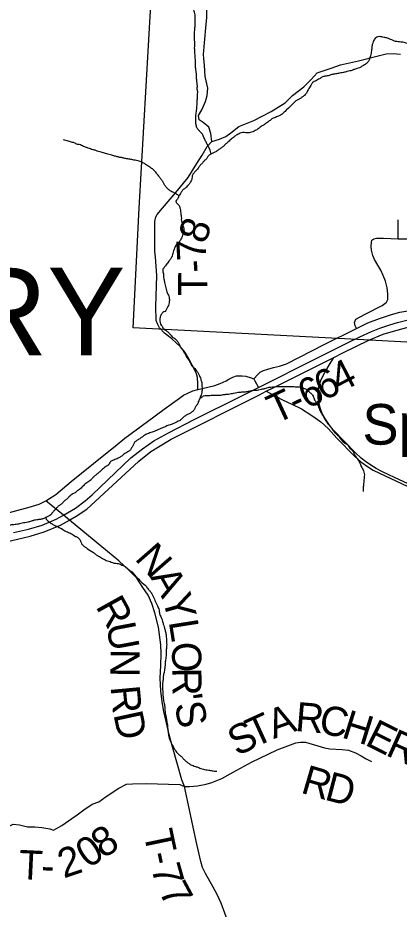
# Model space of a CAD drawing. Extents: x -20.2 to 34, y 0 to 22.
# Drawn here: x 4.435 to 5.177, y 14.901 to 16.636 of the extents above; entities that cross this region are included whole.
import ezdxf

# ---------------------------------------------------------------- set-up
doc = ezdxf.new("R2010")
doc.units = 0
for name, color, linetype in [('GM_X_County_Road', 7, 'Continuous'), ('GM_X_Minor_River', 7, 'Continuous'), ('GM_X_Section', 7, 'Continuous'), ('GM_X_State_Route', 7, 'Continuous'), ('GM_X_Township_Road', 7, 'Continuous'), ('GM_X_Township_Road_Text', 7, 'Continuous'), ('GM_X_Township_Text', 7, 'Continuous'), ('GM_X_Unincorporated_Text', 7, 'Continuous'), ('GM_X_US_Route', 7, 'Continuous')]:
    doc.layers.add(name, color=color, linetype=linetype)

msp = doc.modelspace()

# ---------------------------------------------------------------- linework, layer by layer
at = {"layer": 'GM_X_County_Road'}
for points in [[(4.4893, 15.6954), (4.5091, 15.7083), (4.5389, 15.7332), (4.6022, 15.7848), (4.6247, 15.8024), (4.6436, 15.8178), (4.6875, 15.8504), (4.7196, 15.8739), (4.7498, 15.8957), (4.7578, 15.9016), (4.7659, 15.9053), (4.7759, 15.9099), (4.7857, 15.9123), (4.8049, 15.917), (4.8188, 15.92), (4.8287, 15.9241), (4.8407, 15.9293), (4.8455, 15.9326), (4.8538, 15.9365), (4.8607, 15.9387), (4.8716, 15.9391), (4.8791, 15.938), (4.8893, 15.9352), (4.8947, 15.9332), (4.8964, 15.9292), (4.9034, 15.9164)], [(4.1832, 15.6019), (4.1857, 15.6029), (4.272, 15.6331), (4.426, 15.6752), (4.4573, 15.6834), (4.4765, 15.6894), (4.4893, 15.6954)]]:
    msp.add_lwpolyline(points, dxfattribs=at)
at = {"layer": 'GM_X_Minor_River'}
for points in [[(4.8114, 16.3706), (4.8086, 16.3802), (4.8049, 16.3871), (4.8015, 16.3943), (4.7981, 16.4008), (4.7952, 16.408), (4.7906, 16.4134), (4.7865, 16.4176), (4.7831, 16.4233), (4.7817, 16.4298), (4.7813, 16.4354), (4.7814, 16.4415), (4.7818, 16.4464), (4.7822, 16.451), (4.783, 16.4563), (4.7838, 16.4635), (4.7842, 16.4696), (4.7843, 16.4741), (4.7847, 16.4813), (4.7847, 16.4859), (4.7852, 16.4901), (4.7844, 16.4965), (4.7845, 16.5037), (4.7838, 16.5106), (4.7831, 16.5193), (4.7831, 16.5235), (4.7824, 16.5296), (4.7817, 16.5345), (4.781, 16.5391), (4.7806, 16.5444), (4.7807, 16.5516), (4.7804, 16.5573), (4.78, 16.5634), (4.7797, 16.5691), (4.7793, 16.574), (4.7794, 16.5858), (4.7791, 16.5922), (4.7793, 16.6123), (4.7797, 16.6169), (4.7801, 16.621), (4.7801, 16.626), (4.7802, 16.6381), (4.7795, 16.6442), (4.7784, 16.6488), (4.7769, 16.6537), (4.7735, 16.6587), (4.7675, 16.6659), (4.7596, 16.6732), (4.7536, 16.6808), (4.7487, 16.6866), (4.7431, 16.6927), (4.7344, 16.7003), (4.7299, 16.7049), (4.7242, 16.7092), (4.7152, 16.7157), (4.7072, 16.7207), (4.7, 16.7241), (4.6944, 16.7276), (4.6895, 16.7292), (4.6834, 16.7303), (4.6762, 16.7312), (4.6713, 16.7312), (4.6663, 16.7309), (4.6621, 16.7301), (4.658, 16.729), (4.6519, 16.7264), (4.6435, 16.7219), (4.6366, 16.7193), (4.6324, 16.7159), (4.6282, 16.7137), (4.6225, 16.7099), (4.6168, 16.7066), (4.6077, 16.7017), (4.6008, 16.6965), (4.5954, 16.6916), (4.5893, 16.6871), (4.5848, 16.6833), (4.579, 16.6792), (4.568, 16.6732), (4.5634, 16.6706), (4.5581, 16.6683), (4.5505, 16.6653), (4.5459, 16.6639), (4.5417, 16.6628), (4.5364, 16.6617), (4.5318, 16.6606), (4.5273, 16.6602), (4.522, 16.6603), (4.5178, 16.6599), (4.5121, 16.6596)], [(5.219, 16.5569), (5.2168, 16.5622), (5.2141, 16.5664), (5.2108, 16.5718), (5.2017, 16.5809), (5.1957, 16.5844), (5.1912, 16.5863), (5.187, 16.5875), (5.1824, 16.5883), (5.1783, 16.5887), (5.1726, 16.5895), (5.1684, 16.5903), (5.1631, 16.593), (5.159, 16.5942), (5.1548, 16.5961), (5.148, 16.5973), (5.1434, 16.5985), (5.1336, 16.5978), (5.1286, 16.5929), (5.1267, 16.5887), (5.1251, 16.5838), (5.1239, 16.5755), (5.1235, 16.5713), (5.1227, 16.5668), (5.1215, 16.5618), (5.1204, 16.5577), (5.1188, 16.5531), (5.1153, 16.5482), (5.11, 16.5441), (5.1054, 16.5415), (5.1001, 16.5385), (5.0948, 16.537), (5.0894, 16.5348), (5.0853, 16.5333), (5.0811, 16.5322), (5.0758, 16.5311), (5.0689, 16.5292), (5.0636, 16.5285), (5.0594, 16.5274), (5.0514, 16.5263), (5.0446, 16.5245), (5.0374, 16.5226), (5.0328, 16.5219), (5.0271, 16.5201), (5.0225, 16.5171), (5.0183, 16.5152), (5.0141, 16.5126), (5.01, 16.5107), (5.0065, 16.5062), (5.0042, 16.502), (5.0015, 16.4979), (4.9969, 16.4892), (4.9915, 16.4835), (4.987, 16.4801), (4.9824, 16.4771), (4.9778, 16.4749), (4.9728, 16.4708), (4.9583, 16.4565), (4.9522, 16.4508), (4.9465, 16.4463), (4.9408, 16.4437), (4.9366, 16.4418), (4.9324, 16.4403), (4.9274, 16.4373), (4.9217, 16.4325), (4.9068, 16.4227), (4.9026, 16.4197), (4.8973, 16.4163), (4.8927, 16.4137), (4.8874, 16.4122), (4.8828, 16.4115), (4.8787, 16.4119), (4.873, 16.4123), (4.868, 16.4109), (4.86, 16.4071), (4.8547, 16.403), (4.8478, 16.3974), (4.8413, 16.3913), (4.8364, 16.3868), (4.8318, 16.3827), (4.826, 16.3793), (4.8215, 16.3756), (4.8158, 16.3726), (4.8108, 16.3703), (4.8058, 16.3666), (4.8031, 16.362), (4.7978, 16.3571), (4.7944, 16.353), (4.7898, 16.3481), (4.7859, 16.3428), (4.781, 16.3375), (4.7771, 16.333), (4.7744, 16.3281), (4.774, 16.3232), (4.7725, 16.3186), (4.7702, 16.3145), (4.7663, 16.3092)], [(4.7489, 16.2888), (4.7434, 16.293), (4.737, 16.2961), (4.7328, 16.2981), (4.7276, 16.3023), (4.723, 16.3072), (4.72, 16.3118), (4.717, 16.3168), (4.7133, 16.3225), (4.7092, 16.3278), (4.7047, 16.3336), (4.699, 16.3401), (4.6918, 16.3451), (4.685, 16.3497), (4.6801, 16.3527), (4.6733, 16.3558), (4.6688, 16.3574), (4.6586, 16.3594), (4.6514, 16.3609), (4.6464, 16.3614), (4.64, 16.3629), (4.6332, 16.3641), (4.6271, 16.3657), (4.6199, 16.3676), (4.6157, 16.3688), (4.6104, 16.37), (4.6059, 16.3715), (4.5972, 16.3739), (4.5919, 16.3754), (4.587, 16.3774), (4.5809, 16.3789), (4.5722, 16.382), (4.565, 16.3844), (4.5571, 16.3882), (4.5514, 16.3894), (4.545, 16.3921), (4.5374, 16.3941), (4.5332, 16.3953), (4.5283, 16.3968), (4.5238, 16.3984)], [(4.7663, 16.3092), (4.7606, 16.3039), (4.7556, 16.3002), (4.7526, 16.2952), (4.7487, 16.2884), (4.7456, 16.2828), (4.7429, 16.2786), (4.7452, 16.2744), (4.7489, 16.2702), (4.7508, 16.2638), (4.7519, 16.2584), (4.7526, 16.2531), (4.7533, 16.2486), (4.7533, 16.2425), (4.754, 16.2372), (4.7555, 16.2326), (4.7574, 16.2284), (4.7585, 16.2231), (4.7584, 16.2185), (4.7557, 16.2125), (4.7542, 16.2083), (4.7507, 16.2015), (4.7465, 16.1966), (4.7423, 16.1929), (4.7404, 16.1887), (4.738, 16.1819), (4.7369, 16.1773), (4.7357, 16.1724), (4.733, 16.1675), (4.7291, 16.1618), (4.7238, 16.155), (4.7207, 16.1509), (4.7176, 16.1464), (4.7172, 16.1414), (4.7183, 16.1373), (4.7183, 16.1327), (4.7194, 16.1274), (4.7205, 16.1205), (4.7216, 16.1156), (4.7231, 16.1099), (4.7245, 16.1049), (4.726, 16.1004), (4.7283, 16.0958), (4.7294, 16.0916), (4.7301, 16.0874), (4.7297, 16.0833), (4.7293, 16.0783), (4.7273, 16.0738), (4.7246, 16.0685), (4.7216, 16.0644), (4.7174, 16.0621), (4.7135, 16.0565), (4.7116, 16.0504), (4.7116, 16.0455), (4.713, 16.0398), (4.7157, 16.0356), (4.7194, 16.0298), (4.7236, 16.0271), (4.7292, 16.0226), (4.733, 16.018), (4.7386, 16.0126), (4.7428, 16.0099), (4.7469, 16.0042), (4.7495, 15.9996), (4.7518, 15.9947), (4.7552, 15.9901), (4.7582, 15.9851), (4.7615, 15.9798), (4.7645, 15.9741), (4.7683, 15.9691), (4.7716, 15.9623), (4.7739, 15.9581), (4.7795, 15.9535), (4.7825, 15.9493), (4.7863, 15.9439), (4.7885, 15.939), (4.7904, 15.9348), (4.7915, 15.9306), (4.793, 15.9257), (4.7933, 15.9211), (4.7937, 15.9154), (4.7936, 15.9112), (4.7932, 15.9067), (4.7917, 15.9014), (4.7901, 15.8972), (4.7882, 15.893), (4.7863, 15.8881), (4.7839, 15.8828), (4.7805, 15.8779), (4.7785, 15.873), (4.7743, 15.8689), (4.7698, 15.8655), (4.7641, 15.8629), (4.7587, 15.8595), (4.7541, 15.855), (4.7495, 15.8516), (4.745, 15.8494)], [(4.7901, 15.8972), (4.7913, 15.8968), (4.7966, 15.8998), (4.8015, 15.9005), (4.8091, 15.9009), (4.8141, 15.9012), (4.8243, 15.9011), (4.8319, 15.9018), (4.8384, 15.9029), (4.8452, 15.9036), (4.8505, 15.9043), (4.8551, 15.9054), (4.8611, 15.9065), (4.8665, 15.9072), (4.8763, 15.9079), (4.8839, 15.909), (4.8896, 15.9101), (4.8949, 15.9108), (4.8991, 15.9108), (4.9037, 15.9115), (4.9094, 15.913), (4.9136, 15.9137), (4.9197, 15.9156), (4.9246, 15.9167), (4.9307, 15.9174), (4.9352, 15.9177), (4.9413, 15.9181), (4.9459, 15.918), (4.9523, 15.918), (4.9584, 15.9183), (4.9698, 15.9182), (4.9751, 15.9178), (4.98, 15.9174), (4.9853, 15.9169), (4.9902, 15.9154), (4.9951, 15.9135), (4.9993, 15.9104), (5.0042, 15.9062), (5.0087, 15.9012), (5.0121, 15.894), (5.0151, 15.8879), (5.0196, 15.8806), (5.0214, 15.8753), (5.0237, 15.8707), (5.0267, 15.865), (5.0308, 15.8581), (5.0386, 15.8456), (5.0432, 15.8406), (5.0462, 15.836), (5.0495, 15.8318), (5.0533, 15.8272), (5.059, 15.8223), (5.065, 15.8142), (5.071, 15.8089), (5.0789, 15.802), (5.0815, 15.7978), (5.0861, 15.7936), (5.0887, 15.789), (5.0921, 15.7833), (5.0969, 15.776), (5.0992, 15.7718), (5.1022, 15.7665), (5.1037, 15.7623), (5.107, 15.7562), (5.1089, 15.7516), (5.1096, 15.7463), (5.1088, 15.7365), (5.1079, 15.7274), (5.1075, 15.7228), (5.1075, 15.7137)], [(4.745, 15.8494), (4.74, 15.8471), (4.7355, 15.8449), (4.7313, 15.8434), (4.7271, 15.8423), (4.7229, 15.8404), (4.7179, 15.8382), (4.7134, 15.8363), (4.7077, 15.8337), (4.7027, 15.8318), (4.6985, 15.83), (4.694, 15.8285), (4.6898, 15.827), (4.6845, 15.8248), (4.6799, 15.8222), (4.6738, 15.8176), (4.6673, 15.8135), (4.6631, 15.8105), (4.66, 15.8052), (4.6573, 15.8003), (4.6543, 15.795), (4.6493, 15.7909), (4.6447, 15.7886), (4.6386, 15.7838), (4.6329, 15.78), (4.6283, 15.7774), (4.6238, 15.7759), (4.6196, 15.774), (4.6146, 15.771), (4.6119, 15.7665), (4.6077, 15.7631), (4.6035, 15.7605), (4.5959, 15.7533), (4.5909, 15.7492), (4.5856, 15.7447), (4.581, 15.7409), (4.5775, 15.7368), (4.5714, 15.7323), (4.5672, 15.7293), (4.5611, 15.7236), (4.555, 15.718), (4.5508, 15.7154), (4.5466, 15.7116), (4.5424, 15.7093), (4.5344, 15.7033), (4.5306, 15.6992), (4.5252, 15.6951), (4.5207, 15.6902), (4.5161, 15.6868), (4.5115, 15.683), (4.5077, 15.6785), (4.5035, 15.6743), (4.4992, 15.6687), (4.495, 15.6661), (4.4897, 15.6634), (4.4855, 15.6612), (4.4791, 15.6597), (4.4718, 15.6587), (4.4669, 15.6579), (4.4612, 15.6561), (4.4547, 15.6542), (4.4487, 15.6531), (4.4433, 15.652), (4.4384, 15.6509), (4.4342, 15.6502), (4.4297, 15.6495), (4.4247, 15.6491), (4.4205, 15.6484), (4.4137, 15.647), (4.4088, 15.6459), (4.4034, 15.644), (4.397, 15.6422), (4.3928, 15.6407), (4.3886, 15.6396), (4.3844, 15.6377), (4.3795, 15.6366), (4.3749, 15.6343), (4.37, 15.6329), (4.3616, 15.6322), (4.3567, 15.6315), (4.3517, 15.6323), (4.3468, 15.6334), (4.3426, 15.6331), (4.3381, 15.632), (4.3327, 15.6301), (4.3282, 15.6279), (4.3209, 15.6241), (4.316, 15.6211), (4.3095, 15.6185), (4.3042, 15.6171), (4.2993, 15.6167), (4.2886, 15.6145), (4.2844, 15.6134), (4.2791, 15.6123), (4.2745, 15.6116), (4.2662, 15.6094), (4.262, 15.6083)], [(4.4897, 15.6634), (4.4897, 15.6627), (4.4965, 15.6543), (4.5006, 15.6516), (4.5059, 15.6485), (4.5108, 15.6462), (4.5157, 15.6435), (4.5203, 15.6416), (4.5244, 15.6385), (4.5293, 15.6362), (4.5339, 15.6343), (4.5384, 15.6319), (4.543, 15.6293), (4.5471, 15.6266), (4.552, 15.6242), (4.5565, 15.6193), (4.558, 15.6147), (4.5606, 15.6101), (4.5648, 15.6067), (4.5697, 15.6032), (4.5822, 15.5952), (4.5863, 15.5917), (4.5916, 15.5883), (4.5958, 15.5863), (4.5999, 15.5836), (4.6052, 15.5809), (4.6094, 15.579), (4.6147, 15.5775), (4.6192, 15.5755), (4.6256, 15.5743), (4.6306, 15.5735), (4.6374, 15.5708), (4.6427, 15.5685), (4.6472, 15.5651), (4.6532, 15.5601), (4.6574, 15.5574), (4.6615, 15.5532), (4.6649, 15.5486), (4.6694, 15.5444), (4.6747, 15.5386), (4.6852, 15.5287), (4.6898, 15.5226), (4.6939, 15.518), (4.6973, 15.5119), (4.6999, 15.5069), (4.7017, 15.502), (4.7044, 15.4967), (4.707, 15.4917), (4.7085, 15.4875), (4.7099, 15.483), (4.711, 15.4761), (4.714, 15.4689), (4.7162, 15.4632), (4.7173, 15.459), (4.7192, 15.4529), (4.7207, 15.4476), (4.7225, 15.4411), (4.7233, 15.4369), (4.724, 15.4301), (4.7243, 15.4251), (4.7246, 15.421), (4.7246, 15.4111), (4.7237, 15.4012), (4.7237, 15.3971), (4.7233, 15.3917), (4.7225, 15.3864), (4.7221, 15.3823), (4.7216, 15.3747), (4.7208, 15.3682), (4.72, 15.3629), (4.7185, 15.3569), (4.718, 15.3508), (4.7172, 15.344), (4.7168, 15.3383), (4.7168, 15.3318), (4.7171, 15.3254), (4.7174, 15.3193), (4.7181, 15.3109), (4.7188, 15.3064), (4.7199, 15.3014), (4.7207, 15.2972), (4.721, 15.2915), (4.7217, 15.2855), (4.7224, 15.2798), (4.7235, 15.2748), (4.725, 15.2672), (4.7257, 15.2623), (4.7264, 15.257), (4.7268, 15.252), (4.7275, 15.2456), (4.7286, 15.2391), (4.7297, 15.2342), (4.7315, 15.2292), (4.7334, 15.225), (4.7364, 15.2193), (4.7394, 15.214), (4.7428, 15.2086)], [(4.7428, 15.2086), (4.7484, 15.2021), (4.7537, 15.1979), (4.7578, 15.1933), (4.7627, 15.1887), (4.7673, 15.1853), (4.7718, 15.1822), (4.7763, 15.1806), (4.7809, 15.1787), (4.7873, 15.1768), (4.7915, 15.1748), (4.7964, 15.1737), (4.8009, 15.1725), (4.8066, 15.1717), (4.8131, 15.1705), (4.8222, 15.1697)]]:
    msp.add_spline(points, degree=3, dxfattribs=at)
at = {"layer": 'GM_X_Section'}
msp.add_lwpolyline([(5.7813, 16.999), (5.7463, 16.4999), (5.7268, 16.1694), (5.7132, 15.9765), (5.0956, 16.0096), (4.6593, 16.0323), (4.6715, 16.2651), (4.6941, 16.6609), (4.7152, 17.053)], close=True, dxfattribs=at)
at = {"layer": 'GM_X_State_Route'}
msp.add_line((5.0503, 15.9748), (5.068, 15.9835), dxfattribs=at)
for points in [[(5.038, 15.9839), (5.0441, 15.987), (5.0779, 16.0039), (5.1009, 16.015), (5.1236, 16.0253), (5.1397, 16.0318), (5.159, 16.0385), (5.1741, 16.0427), (5.1949, 16.0477), (5.2159, 16.0515), (5.2377, 16.0534), (5.266, 16.0542), (5.2864, 16.0538), (5.3466, 16.0495), (5.3739, 16.0465), (5.3908, 16.045), (5.4035, 16.0438), (5.4473, 16.0399), (5.4997, 16.0343), (5.5459, 16.0297), (5.5577, 16.0285), (5.5796, 16.0263)], [(5.068, 15.9835), (5.1183, 16.0083), (5.1461, 16.0201), (5.1663, 16.0262), (5.1921, 16.0329), (5.2125, 16.0367), (5.2464, 16.0404), (5.2644, 16.0406), (5.2792, 16.0403), (5.2902, 16.0399), (5.3256, 16.0371), (5.3442, 16.0353)], [(4.524, 15.6675), (4.5473, 15.6815), (4.5659, 15.6956), (4.5797, 15.7071), (4.6553, 15.7794), (4.6777, 15.797), (4.7, 15.8125), (4.7286, 15.8283), (4.7785, 15.8537), (4.8713, 15.9003), (4.9034, 15.9164), (5.017, 15.9734), (5.038, 15.9839)], [(4.9187, 15.9089), (4.9336, 15.9163), (5.0503, 15.9748)], [(4.5362, 15.6587), (4.5487, 15.6659), (4.5691, 15.6798), (4.5942, 15.702), (4.6704, 15.773), (4.6939, 15.7916), (4.7089, 15.8009), (4.7336, 15.8155), (4.9039, 15.9015), (4.9187, 15.9089)], [(4.9187, 15.9089), (4.9501, 15.8924), (4.9682, 15.8836), (4.9871, 15.8745), (5.0071, 15.862), (5.025, 15.8496), (5.0397, 15.8356), (5.056, 15.8176), (5.0903, 15.7824), (5.103, 15.7716), (5.1174, 15.7615), (5.1269, 15.7553), (5.2604, 15.6923)], [(4.4268, 15.6341), (4.4559, 15.6407), (4.4821, 15.6485), (4.5096, 15.66), (4.524, 15.6675)], [(4.4123, 15.6162), (4.4588, 15.627), (4.4865, 15.6355), (4.5181, 15.6482), (4.5353, 15.6582), (4.5362, 15.6587)]]:
    msp.add_lwpolyline(points, dxfattribs=at)
at = {"layer": 'GM_X_Township_Road'}
msp.add_line((5.1753, 16.2056), (5.1752, 16.2423), dxfattribs=at)
for points in [[(4.7972, 16.5716), (4.7983, 16.5871), (4.8016, 16.623), (4.803, 16.6358), (4.803, 16.6597), (4.7924, 16.6806), (4.7713, 16.7035), (4.7587, 16.7182), (4.7453, 16.7408), (4.72, 16.8009), (4.7007, 16.8328), (4.6845, 16.8611), (4.6794, 16.8678), (4.6698, 16.8735), (4.6652, 16.8846), (4.6581, 16.8957)], [(4.7028, 16.1699), (4.7018, 16.1817), (4.7016, 16.2283), (4.702, 16.2394), (4.7035, 16.2482), (4.7061, 16.2532), (4.7166, 16.2653), (4.7425, 16.2957), (4.7668, 16.3248), (4.7838, 16.352), (4.7939, 16.3682), (4.8034, 16.385), (4.8128, 16.3948), (4.8279, 16.3996), (4.8397, 16.405), (4.85, 16.4117), (4.8651, 16.4241), (4.8947, 16.4356), (4.9279, 16.4536), (4.9556, 16.47), (4.9698, 16.4843), (4.992, 16.5012), (5.0058, 16.5157), (5.0176, 16.5289), (5.0447, 16.5378), (5.0633, 16.5443), (5.0979, 16.5519), (5.1364, 16.5615), (5.152, 16.5655), (5.1657, 16.5665), (5.1797, 16.5649)], [(4.8128, 16.3948), (4.811, 16.4102), (4.8067, 16.4229), (4.7961, 16.432), (4.7883, 16.4371), (4.7865, 16.4455), (4.7931, 16.4568), (4.8004, 16.4725), (4.8034, 16.4846), (4.8046, 16.4985), (4.7995, 16.5212), (4.7983, 16.5432), (4.7974, 16.5559), (4.7967, 16.565), (4.7972, 16.5716)], [(5.1244, 16.2028), (5.1281, 16.2054), (5.133, 16.207), (5.1378, 16.2069), (5.1419, 16.2069), (5.1469, 16.2066), (5.1753, 16.2056), (5.2278, 16.2055), (5.2333, 16.207), (5.2365, 16.2102), (5.2391, 16.2147), (5.2428, 16.2299), (5.2457, 16.2442), (5.2472, 16.2563), (5.2466, 16.262), (5.2457, 16.2687), (5.2408, 16.291)], [(5.1529, 16.0825), (5.1551, 16.0873), (5.155, 16.0984), (5.1538, 16.1103), (5.1506, 16.1229), (5.1464, 16.1339), (5.1419, 16.1446), (5.1356, 16.1542), (5.1291, 16.1654), (5.1258, 16.1731), (5.1237, 16.1832), (5.123, 16.1909), (5.1233, 16.1989), (5.1244, 16.2028)], [(4.7857, 15.9123), (4.7854, 15.9235), (4.7848, 15.936), (4.783, 15.9427), (4.7804, 15.9484), (4.768, 15.972), (4.7607, 15.9842), (4.7514, 15.9957), (4.7346, 16.0107), (4.7207, 16.0222), (4.7111, 16.0326), (4.7073, 16.0386), (4.7045, 16.0467), (4.7039, 16.0737), (4.7057, 16.1344), (4.7028, 16.1699)], [(5.0945, 16.0312), (5.0916, 16.0363), (5.0904, 16.0426), (5.0929, 16.0493), (5.1013, 16.054), (5.1123, 16.0596), (5.144, 16.0757), (5.1524, 16.0816), (5.1529, 16.0825)], [(4.8947, 15.9332), (4.9022, 15.9415), (4.9071, 15.9459), (4.9131, 15.9492), (4.9216, 15.952), (4.9328, 15.9553), (4.9447, 15.9575), (4.9579, 15.9625), (5.0311, 16.0002), (5.0945, 16.0312), (5.1164, 16.0419), (5.1392, 16.0508), (5.1627, 16.0581), (5.1785, 16.0627), (5.2018, 16.067), (5.2295, 16.0702), (5.2475, 16.0718), (5.2536, 16.0717)], [(4.8597, 14.835), (4.8306, 14.9131), (4.8228, 14.9296), (4.815, 14.9438), (4.8002, 14.9703), (4.7948, 14.9821), (4.791, 14.994), (4.7824, 15.0333), (4.7652, 15.1125), (4.7592, 15.1397), (4.7544, 15.1529), (4.7358, 15.2173), (4.7304, 15.2381), (4.7194, 15.2855), (4.7159, 15.3044), (4.7137, 15.3262), (4.7124, 15.3507), (4.7134, 15.3752), (4.714, 15.3979), (4.7134, 15.4154), (4.7086, 15.4496), (4.7018, 15.4776), (4.6959, 15.4959), (4.6887, 15.5123), (4.6785, 15.5273), (4.6666, 15.545), (4.652, 15.5601), (4.6315, 15.5787), (4.5353, 15.6582), (4.524, 15.6675), (4.4893, 15.6954)], [(4.7592, 15.1397), (4.7695, 15.14), (4.7851, 15.1414), (4.8015, 15.1443), (4.8127, 15.1474), (4.832, 15.1555), (4.8543, 15.1676), (4.8898, 15.1874), (4.9401, 15.2109), (4.9764, 15.2248), (4.9856, 15.2264), (4.9951, 15.2262), (5.0321, 15.2149), (5.0421, 15.2131), (5.0663, 15.2118), (5.0787, 15.2104), (5.0922, 15.2052), (5.1034, 15.1992), (5.1129, 15.1938), (5.1233, 15.1884)], [(4.5466, 15.0819), (4.5477, 15.0828), (4.5634, 15.0941), (4.5796, 15.1054), (4.5927, 15.1098), (4.6067, 15.1201), (4.6315, 15.1368), (4.6463, 15.1446), (4.6585, 15.1451), (4.6846, 15.1457), (4.7501, 15.1435), (4.7592, 15.1397)], [(4.4133, 15.0595), (4.417, 15.0617), (4.426, 15.0664), (4.4381, 15.0653), (4.4541, 15.0611), (4.4681, 15.0615), (4.4818, 15.0599), (4.4971, 15.0575), (4.5047, 15.055), (4.5209, 15.0642), (4.5466, 15.0819)]]:
    msp.add_lwpolyline(points, dxfattribs=at)
at = {"layer": 'GM_X_US_Route'}
msp.add_line((5.0503, 15.9748), (5.068, 15.9835), dxfattribs=at)
for points in [[(5.068, 15.9835), (5.1183, 16.0083), (5.1461, 16.0201), (5.1663, 16.0262), (5.1921, 16.0329), (5.2125, 16.0367), (5.2464, 16.0404), (5.2644, 16.0406), (5.2792, 16.0403), (5.2902, 16.0399), (5.3256, 16.0371), (5.3442, 16.0353)], [(5.2816, 15.6889), (5.1682, 15.7412), (5.157, 15.7461), (5.145, 15.752), (5.1327, 15.7588), (5.1225, 15.765), (5.1118, 15.7721), (5.1031, 15.779), (5.0921, 15.7892), (5.0491, 15.8341), (5.0417, 15.8431), (5.0325, 15.8564), (5.0278, 15.8658), (5.024, 15.8747), (5.0215, 15.8837), (5.0199, 15.8959), (5.0199, 15.9076), (5.0212, 15.9194), (5.0261, 15.9329), (5.0325, 15.9453), (5.0413, 15.9597), (5.0503, 15.9748)]]:
    msp.add_lwpolyline(points, dxfattribs=at)

# ---------------------------------------------------------------- texts
at = {"layer": 'GM_X_Township_Road_Text'}
for s, rotation, p in [('8', 70.3406, (4.7994, 16.1935)), ('7', 93.1031, (4.8022, 16.1644)), ('-', 94.0448, (4.8038, 16.1414)), ('T', 89.5157, (4.8036, 16.094)), ('4', 27.1671, (5.0615, 15.9051)), ('6', 26.3323, (4.9981, 15.8733)), ('6', 26.9793, (5.0301, 15.8892)), ('T', 24.8341, (4.937, 15.8447)), ('-', 25.6834, (4.9764, 15.8629)), ('N', 311.1592, (4.661, 15.5825)), ('A', 299.5199, (4.6921, 15.5473)), ('R', 299.0444, (4.5856, 15.4904)), ('Y', 285.8318, (4.7154, 15.5071)), ('U', 280.7363, (4.6067, 15.4541)), ('L', 278.9938, (4.7286, 15.4608)), ('O', 270.6266, (4.7351, 15.421)), ('N', 269.2787, (4.6157, 15.4079)), ('R', 270.6464, (4.7356, 15.371)), ('R', 275.2462, (4.6154, 15.3341)), ("'", 278.6398, (4.7369, 15.3157)), ('S', 282.1367, (4.7394, 15.2996)), ('R', 355.131, (4.974, 15.2479)), ('D', 282.1794, (4.6208, 15.2803)), ('T', 24.5138, (4.8957, 15.2149)), ('A', 19.4061, (4.9331, 15.2321)), ('C', 349.219, (5.019, 15.2441)), ('H', 342.6479, (5.0632, 15.2358)), ('S', 27.0092, (4.8621, 15.1978)), ('E', 333.2625, (5.1086, 15.2218)), ('R', 335.8463, (5.1491, 15.2015)), ('R', 343.7378, (4.9838, 15.1281)), ('D', 345.318, (5.0302, 15.1146)), ('8', 32.6177, (4.601, 14.9985)), ('T', 281.8218, (4.6794, 15.0501)), ('0', 33.8516, (4.5722, 14.9792)), ('2', 18.6941, (4.5244, 14.9607)), ('T', 357.196, (4.4358, 14.9599)), ('-', 282.118, (4.6882, 15.0082)), ('7', 285.7714, (4.694, 14.9816)), ('-', 359.1678, (4.4803, 14.9578)), ('7', 298.1358, (4.7084, 14.9358))]:
    msp.add_text(s, height=0.0568, rotation=rotation, dxfattribs=at).set_placement(p)
at = {"layer": 'GM_X_Township_Text'}
msp.add_text('SALISBURY', height=0.17045, rotation=0, dxfattribs=at).set_placement((3.365, 15.9788))
at = {"layer": 'GM_X_Unincorporated_Text'}
msp.add_text('Springs', height=0.07898, rotation=0, dxfattribs=at).set_placement((5.1058, 15.8051))

doc.saveas('drawing.dxf')
